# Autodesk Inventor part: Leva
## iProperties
Created: 2008-01
Part Number: Leva
Document SubType Name: Modeling
Designer: eruiz-tagle
Mass: 0.488837 g
Surface Area: 12.3985 cm^2
Volume: 0.488837 cm^3
Density: 1 g/cm^3
Author: eruiz-tagle
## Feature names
1. Extrusion1
2. Extrusion2
3. Mirror1
4. Rectangular Pattern1
